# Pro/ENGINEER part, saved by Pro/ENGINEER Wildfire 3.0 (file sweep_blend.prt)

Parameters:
  RAJZSZAM = "SWEEP_BLEND"
  ANYAG = "S355J2G3-EN10025"
  PROI_VERSION = "0"
  PROI_CREATED_ON = "2004.08.30. 12:24:55"
  PTC_MATERIAL_NAME = "SZERK_ACEL_BLOKK"

Other parameters: TOMEG, OBJ_TIPUS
